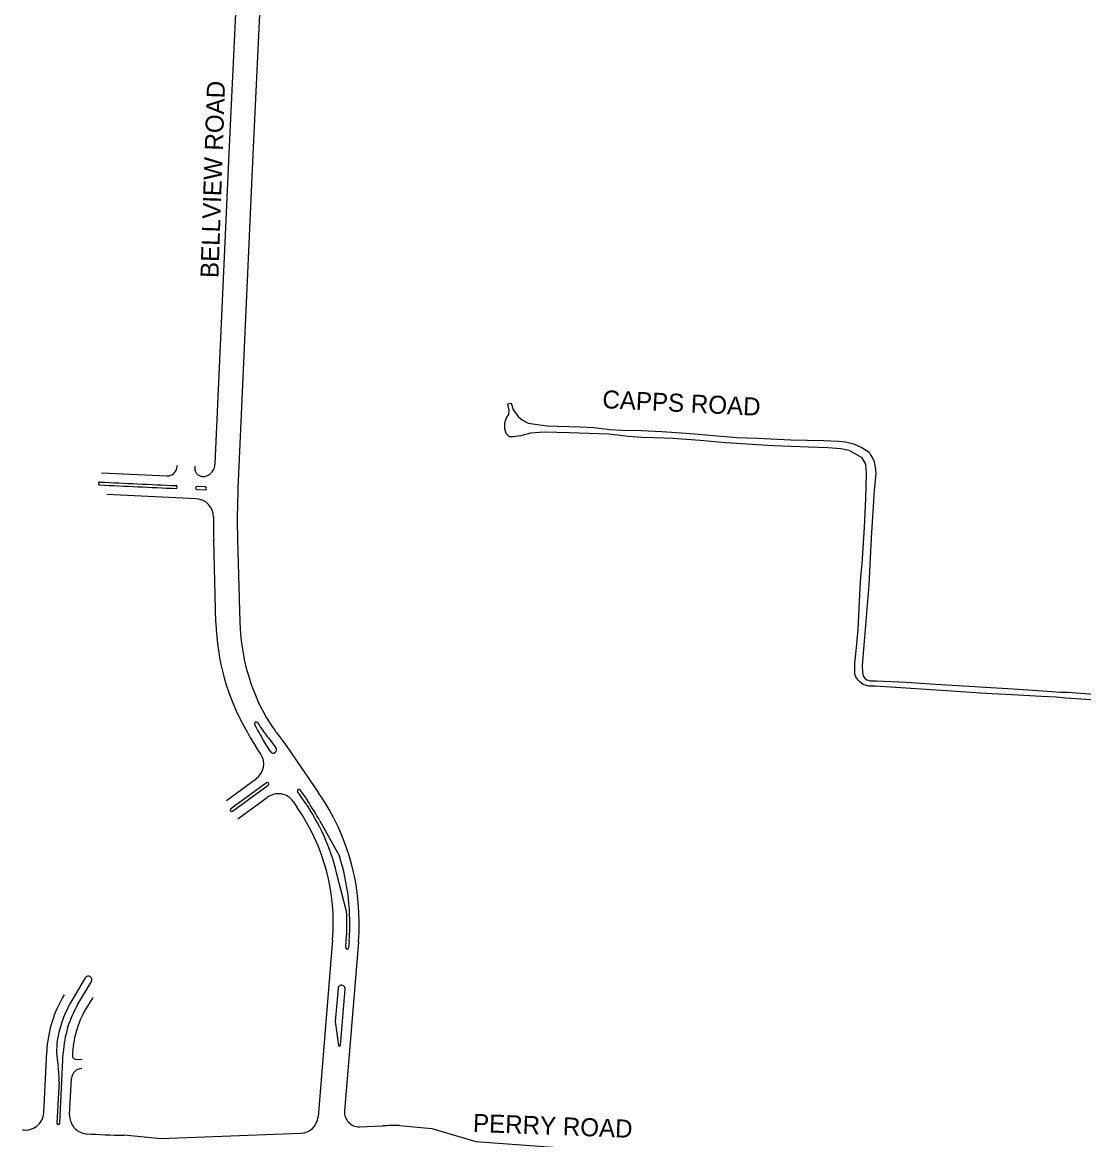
# Model space of a CAD drawing. Extents: x 0 to 712119, y 0 to 761125.
# Drawn here: x 671576 to 674515, y 723620 to 726715 of the extents above; entities that cross this region are included whole.
import ezdxf

# ---------------------------------------------------------------- set-up
doc = ezdxf.new("R2010")
doc.units = 0
doc.layers.add('PAVED ROADS', color=7, linetype='Continuous')
doc.layers.add('street names', color=7, linetype='Continuous')

msp = doc.modelspace()

# ---------------------------------------------------------------- linework, layer by layer
at = {"layer": 'PAVED ROADS'}
for points in [[(672110, 725493), (672148.4, 726352.1), (672185.5, 727127.7)], [(672251.4, 727124.8), (672214.4, 726349.1), (672172.9, 725423.6)], [(674562.5, 724836.5), (674494, 724841), (674466.5, 724843), (674440, 724845.5), (674399, 724847.5), (674317.5, 724852.5), (674278.5, 724854.5), (674230, 724857), (674149.5, 724862.5), (673939, 724876), (673920, 724876.5), (673904.5, 724881), (673896.5, 724887), (673891, 724893), (673884, 724902.5), (673881.5, 724910.5), (673882, 724939.5), (673885.5, 724974), (673890.5, 725033.5), (673895.5, 725130), (673898.5, 725179.5), (673902, 725215.5), (673908, 725315.5), (673912, 725396.5), (673914, 725465.5), (673912, 725491.5), (673901.5, 725509), (673880.5, 725521), (673865.5, 725529), (673842.5, 725533.5), (673806.5, 725536), (673753.5, 725538), (673655, 725542), (673524, 725550), (673453, 725556.5), (673377.5, 725562.5), (673352.5, 725563.5), (673293.5, 725565.5), (673254.5, 725567.5), (673199, 725574), (673091, 725578), (673021.5, 725580), (672983, 725577.5), (672956, 725570), (672935, 725566.5), (672925, 725567), (672916, 725576), (672912.5, 725589), (672912, 725606), (672916.5, 725619.5), (672923.5, 725628.5), (672924.5, 725639.5), (672921.5, 725653), (672920.5, 725658), (672930, 725660.5), (672935.5, 725643), (672940.5, 725634), (672950, 725622.5), (672961, 725613), (672977, 725605), (672996, 725602), (673029, 725597.5), (673057, 725596.5), (673121, 725595), (673158.5, 725593), (673202.5, 725587.5), (673235, 725585), (673290.5, 725584.5), (673347, 725581.5), (673413.5, 725577.5), (673448, 725574), (673511, 725568.5), (673554.5, 725565.5), (673612, 725563.5), (673704.5, 725559), (673795, 725556.5), (673836, 725555), (673855.5, 725553), (673877.5, 725547.5), (673901, 725537.5), (673921, 725524.5), (673925, 725517), (673934, 725501), (673938, 725482.5), (673940, 725466), (673935.5, 725418), (673927, 725287), (673920, 725156), (673906.5, 724989.5), (673902, 724932.5), (673902.5, 724914.5), (673904.5, 724904), (673909, 724898.5), (673915, 724893.5), (673925, 724891), (673941.5, 724891), (674024, 724887), (674105.5, 724882), (674320, 724869), (674402.5, 724863.5), (674450, 724859.5), (674472, 724859.5), (674543.5, 724854.5)], [(672004.4, 725484.3), (672004.5, 725487.3)], [(671795.3, 725467), (671976.2, 725458.6)], [(672053.2, 725484.1), (672053.1, 725482)], [(672001, 725431.9), (672001, 725431.9)], [(672082.4, 725428.1), (672059.5, 725429.2), (672059.5, 725429.2)], [(672057.9, 725395.2), (671810, 725406.7)], [(672059.2, 725421.2), (672082, 725420.1)], [(672111.9, 725052), (672105.7, 725280.2)], [(672171.7, 725282), (672177.9, 725053.8)], [(672279.2, 724748.2), (672308, 724709.1), (672396.4, 724581)], [(672262.7, 724695.1), (672244.7, 724724.2), (672244.7, 724724.3)], [(672257.1, 724732.7), (672277.9, 724705.6)], [(672236.2, 724687.6), (672222.4, 724709)], [(672275.9, 724692.7), (672275.4, 724692.4)], [(672140.7, 724559.7), (672223.8, 724620.2)], [(672252.3, 724608.8), (672152.8, 724536.3)], [(672157.5, 724529.8), (672257, 724602.3)], [(672344.5, 724589.2), (672365.1, 724559.4)], [(672172.8, 724508.8), (672255, 724568.7)], [(672358.5, 724554.9), (672338, 724584.7)], [(672325.6, 724556.7), (672337.1, 724540.1)], [(672399.7, 724502.8), (672453.9, 724405.7)], [(672474, 724252.3), (672446.3, 724358.8)], [(672435, 724173.8), (672394.7, 723682.9)], [(672506.7, 724167.9), (672468.3, 723699)], [(672471.3, 724152.4), (672472.8, 724170.7)], [(672480.8, 724170), (672479.3, 724151.8)], [(671749.9, 724068.5), (671712.4, 724005.2)], [(671729.6, 723995), (671767.1, 724058.3)], [(672450, 724038.8), (672442.5, 723947.1), (672451.2, 723881.7)], [(672457.2, 723881.9), (672469.9, 724037.2), (672469.9, 724037.2)], [(671770.6, 724014.2), (671751.5, 723982)], [(671634.8, 723694), (671643.2, 723863.1)], [(671679.4, 723665.5), (671689.1, 723860.8)], [(671673.1, 723835.3), (671674.9, 723824.1)], [(671723.4, 723843.1), (671741.3, 723842.2)], [(671706.6, 723688.4), (671711.6, 723789.1)], [(671677.2, 723782.4), (671671.5, 723666.6)], [(672620.7, 723659.5), (672710, 723650.5), (672831.5, 723615.3), (673120.5, 723594), (673365.5, 723576.5), (673543, 723566), (673680, 723559.5), (673837, 723550), (673968.5, 723544), (674235.5, 723532), (674563.5, 723518), (674831, 723505), (675184.5, 723489.5), (675351, 723482), (675579.5, 723471), (675797, 723462.5), (675942, 723456), (676139.8, 723447.7), (676367.5, 723438.5)], [(672346.8, 723637.5), (671959.6, 723622.7), (671857.3, 723632.4)], [(672509.7, 723655.8), (672573.6, 723658.3)]]:
    msp.add_lwpolyline(points, dxfattribs=at)
for centre, radius, start, end in [((672072, 725494.2), 38, 283.2598, 358.1523), ((671977.4, 725485.6), 27, 267.356, 357.3472), ((672077, 725480.9), 24, 177.3587, 198.8351), ((672054.2, 725484.1), 1, 87.3587, 177.3587), ((672077, 725480.9), 24, 198.8351, 278.8296), ((671790.3, 725437.6), 4, 94.9717, 274.9782), ((679943.1, 900033), 174781.7, 267.326323, 267.395569), ((675871.1, 811035.3), 85698.9, 267.270926, 267.411444), ((672000.7, 725427.9), 4, 268.9266, 85.7908), ((672059.1, 725425.2), 4, 85.1656, 270.1147), ((672082.2, 725424.1), 4, 267.3587, 87.3587), ((674138, 725335.7), 1967, 177.4367, 181.5639), ((672055, 725345.3), 50, 359.743, 86.6696), ((674138, 725335.7), 2033, 179.7356, 181.5639), ((672744.7, 725069.3), 567, 181.5639, 209.6798), ((672744.7, 725069.3), 633, 181.5639, 209.6804), ((672223.5, 724772), 5, 32.6448, 206.7653), ((672763.6, 725118), 636.4, 212.6448, 217.2553), ((672753, 725096), 587.8, 211.5457, 216.2817), ((672736.1, 725043.9), 613.2, 208.0168, 213.0975), ((672728.1, 725026.5), 570.1, 206.7653, 212.0141), ((672194.1, 724660.5), 50, 306.3841, 32.8205), ((672270.3, 724699.8), 9, 211.6186, 304.5997), ((672270.8, 724700.1), 9, 304.5997, 37.5512), ((672254.7, 724605.6), 4, 306.0847, 126.0847), ((672341.3, 724586.9), 4, 34.5999, 214.5999), ((672284.5, 724528.3), 50, 34.5997, 126.0847), ((671872.8, 724219.9), 598, 28.2396, 34.5997), ((671872.8, 724219.9), 636, 355.3134, 34.5997), ((672155.2, 724533), 4, 126.0975, 306.0718), ((671872.8, 724219.9), 564, 355.3134, 34.5997), ((671872.8, 724219.9), 590, 13.6152, 34.5997), ((671872.8, 724219.9), 610, 355.3134, 17.7353), ((671872.8, 724219.9), 602, 355.3134, 3.0883), ((672475.3, 724152.1), 4, 175.3134, 355.3134), ((671758.5, 724063.4), 10, 329.3226, 149.2967), ((672459.9, 724038), 10, 355.3134, 175.3134), ((671979.8, 723846.4), 337.1, 148.8457, 177.1608), ((671979.8, 723846.4), 311, 149.2967, 169.5229), ((671979.8, 723846.4), 291, 149.2967, 177.1618), ((671979.8, 723846.4), 265.5, 149.2967, 178.6198), ((671869.6, 723866.8), 199, 169.5229, 189.0965), ((672454.2, 723882.1), 3, 187.6214, 355.3128), ((671723.8, 723852.6), 9.5, 178.6198, 267.1618), ((671475.8, 723792.3), 201.6, 357.1902, 9.0871), ((671740.6, 723787.7), 29, 89.7009, 177.1618), ((671584.9, 723696.6), 50, 259.3941, 357.05), ((672508.1, 723695.8), 40, 175.3134, 272.2001), ((671871.5, 725223.6), 1687.7, 246.1353, 260.2379), ((671675.5, 723666), 4.01, 172.4305, 352.4305), ((671756.6, 723686.4), 50, 177.7197, 217.5521), ((672344.9, 723687.5), 50, 272.2001, 354.702), ((672650.8, 721647.7), 2012, 90.8571, 92.2001), ((671756.6, 723686.4), 50, 217.55, 226.2882), ((671756.6, 723686.4), 50, 226.2882, 265.8098), ((671868.1, 725209.3), 1577, 265.8098, 269.606)]:
    msp.add_arc(centre, radius, start, end, dxfattribs=at)

# ---------------------------------------------------------------- texts
at = {"layer": 'street names'}
for s, rotation, p in [('BELLVIEW ROAD', 88.0342, (672118.7, 726006.3)), ('CAPPS ROAD', 357.1968, (673181.4, 725646.4)), ('PERRY ROAD', 357.8093, (672823.2, 723641.7))]:
    msp.add_text(s, height=50, rotation=rotation, dxfattribs=at).set_placement(p)

doc.saveas('drawing.dxf')
